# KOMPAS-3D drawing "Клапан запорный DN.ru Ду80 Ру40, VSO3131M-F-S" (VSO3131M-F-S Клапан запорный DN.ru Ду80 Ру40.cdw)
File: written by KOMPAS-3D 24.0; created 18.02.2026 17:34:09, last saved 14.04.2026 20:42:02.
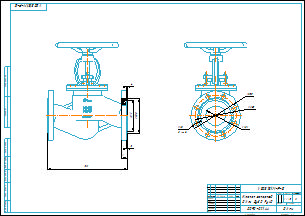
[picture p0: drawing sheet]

Document properties: Автор: R2D2; Форматы листов документа: A2; Полное имя файла: VSO3131M-F-S Клапан запорный DN.ru Ду80 Ру40.m3d; Масса: 22.29; Наименование: Клапан запорный DN.ru Ду80 Ру40; Количество листов документа: 1; Примечание: D090-02144

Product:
- Part/product: Клапан запорный DN.ru Ду80 Ру40  | designation VSO3131M-F-S
    Масса: 22.29
    Раздел спецификации: Прочие изделия
    Примечание: D090-02144

Views: Проекционный вид 2
Referenced files in E:\Работа\Зайцев\VSO3131M-F-S Клапан запорный DN.ru Ду15-100 Ру40\DN50\: VSO3131M-F-S Клапан запорный DN.ru Ду50 Ру40.m3d
Referenced files in E:\Работа\Зайцев\Для компаса\: чертеж DN.ru А3.cdt
Referenced files in E:\Работа\Зайцев\VSO3131M-F-S Клапан запорный DN.ru Ду15-100 Ру40\DN80\: VSO3131M-F-S Клапан запорный DN.ru Ду80 Ру40.m3d
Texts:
  VSO3131M-F-S
  чертеж DN.ru А3.cdt
  Клапан запорный
  DN.ru Ду80 Ру40
  Клапан запорный DN.ru Ду80 Ру40
  VSO3131M-F-S Клапан запорный DN.ru Ду80 Ру40
Dimensions and other numbers on the sheet: 0; 3; 4; 195; 160; 80; 18; 8 отв.; 1:2; 1; 2; 22,29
